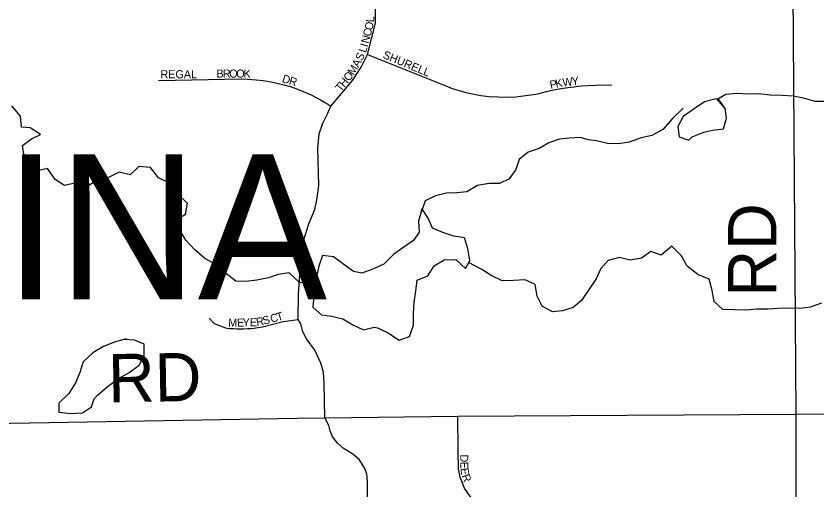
# Model space of a CAD drawing. Extents: x 1985906 to 2277390, y 930619 to 1324581.
# Drawn here: x 2148429 to 2153402, y 1155327 to 1158270 of the extents above; entities that cross this region are included whole.
import ezdxf

# ---------------------------------------------------------------- set-up
doc = ezdxf.new("R2010")
doc.units = 0
for name, color, linetype in [('GM_X_County_Road', 7, 'Continuous'), ('GM_X_County_Road_Text', 7, 'Continuous'), ('GM_X_Minor_Lake', 7, 'Continuous'), ('GM_X_Minor_River', 7, 'Continuous'), ('GM_X_Township_Road', 7, 'Continuous'), ('GM_X_Township_Road_Text', 7, 'Continuous'), ('GM_X_Township_Subdivision', 7, 'Continuous'), ('GM_X_Township_Subdivision_Text', 7, 'Continuous'), ('GM_X_Township_Text', 7, 'Continuous')]:
    doc.layers.add(name, color=color, linetype=linetype)

msp = doc.modelspace()

# ---------------------------------------------------------------- linework, layer by layer
at = {"layer": 'GM_X_County_Road'}
msp.add_lwpolyline([(2145952.7, 1155701.2), (2146258.9, 1155705.5), (2150174.8, 1155772.6), (2150347, 1155774.5), (2151172.5, 1155785.7), (2153272.3, 1155797.3), (2157154.1, 1155842.4)], dxfattribs=at)
at = {"layer": 'GM_X_Minor_Lake'}
for points in [[(2152782.6, 1157753.4), (2152776.9, 1157756.3), (2152705, 1157738.2), (2152639.1, 1157694.1), (2152571.3, 1157646), (2152539.3, 1157583.9), (2152547.3, 1157519.8), (2152607.3, 1157499.8)], [(2152607.3, 1157499.8), (2152627.2, 1157519.8), (2152699.1, 1157549.9), (2152753.1, 1157562), (2152821, 1157570), (2152840.9, 1157636.1), (2152832.9, 1157696.2), (2152790.9, 1157754.3)], [(2152607.3, 1157499.8), (2152627.2, 1157519.8), (2152699.1, 1157549.9), (2152753.1, 1157562), (2152821, 1157570), (2152840.9, 1157636.1), (2152832.9, 1157696.2), (2152782.6, 1157753.4)], [(2150949.6, 1157074.3), (2150949.6, 1157068.2), (2150927.7, 1156996.1), (2150931.7, 1156928), (2150897.8, 1156875.9), (2150835.9, 1156835.8), (2150774, 1156791.7), (2150712.1, 1156729.6), (2150644.2, 1156697.5), (2150576.3, 1156673.4), (2150524.3, 1156683.4), (2150464.4, 1156727.4), (2150400.5, 1156775.5), (2150332.6, 1156783.5), (2150308.6, 1156717.3), (2150294.7, 1156649.2), (2150282.7, 1156583.1), (2150278.7, 1156531), (2150270.8, 1156462.9), (2150324.7, 1156414.8), (2150388.6, 1156406.9), (2150458.5, 1156388.9), (2150520.5, 1156352.8), (2150586.4, 1156320.8), (2150652.3, 1156338.9)], [(2150945, 1157050.5), (2150949.6, 1157068.2), (2150927.7, 1156996.1), (2150931.7, 1156928), (2150897.8, 1156875.9), (2150835.9, 1156835.8), (2150774, 1156791.7), (2150712.1, 1156729.6), (2150644.2, 1156697.5), (2150576.3, 1156673.4), (2150524.3, 1156683.4), (2150464.4, 1156727.4), (2150400.5, 1156775.5), (2150332.6, 1156783.5), (2150308.6, 1156717.3), (2150294.7, 1156649.2), (2150282.7, 1156583.1), (2150278.7, 1156531), (2150270.8, 1156462.9), (2150324.7, 1156414.8), (2150388.6, 1156406.9), (2150458.5, 1156388.9), (2150520.5, 1156352.8), (2150586.4, 1156320.8), (2150652.3, 1156338.9)], [(2150652.3, 1156338.9), (2150672.3, 1156334.9), (2150736.2, 1156304.9), (2150808.1, 1156256.8), (2150872, 1156280.9), (2150896, 1156351), (2150896, 1156423.1), (2150901.9, 1156493.3), (2150911.9, 1156561.4), (2150919.8, 1156629.5), (2150985.7, 1156657.6), (2151025.7, 1156719.7), (2151087.6, 1156755.8), (2151159.5, 1156757.8), (2151219.4, 1156701.8), (2151247.4, 1156751.9), (2151233.4, 1156826), (2151213.3, 1156892.1), (2151147.4, 1156904.1), (2151079.5, 1156926.1), (2151015.6, 1156952.1), (2150987.6, 1157014.2), (2150949.6, 1157074.3)], [(2149112.4, 1156266), (2149040.5, 1156245.9), (2148972.6, 1156217.8), (2148904.7, 1156177.7), (2148844.8, 1156123.6), (2148824.8, 1156055.5), (2148798.9, 1155991.4), (2148757, 1155925.2), (2148695.1, 1155867.1), (2148695.1, 1155811), (2148769, 1155801), (2148840.9, 1155805.1), (2148896.8, 1155843.2), (2148914.8, 1155893.3)], [(2149096.4, 1156262), (2149040.5, 1156245.9), (2148972.6, 1156217.8), (2148904.7, 1156177.7), (2148844.8, 1156123.6), (2148824.8, 1156055.5), (2148798.9, 1155991.4), (2148757, 1155925.2), (2148695.1, 1155867.1), (2148695.1, 1155811), (2148769, 1155801), (2148840.9, 1155805.1), (2148896.8, 1155843.2), (2148914.8, 1155893.3)], [(2148914.8, 1155893.3), (2148936.7, 1155917.3), (2149002.6, 1155973.4), (2149064.5, 1156019.6), (2149128.4, 1156053.6), (2149194.3, 1156101.8), (2149224.3, 1156161.9), (2149224.2, 1156232), (2149164.3, 1156258), (2149096.4, 1156262)]]:
    msp.add_lwpolyline(points, dxfattribs=at)
at = {"layer": 'GM_X_Minor_River'}
for points in [[(2153457.2, 1157739.7), (2153391.3, 1157740.2), (2153318.9, 1157760.6), (2153254.7, 1157773.1), (2153186.7, 1157777.6), (2153112.8, 1157779.8), (2153042.7, 1157786.2), (2152976.9, 1157784.7), (2152904.9, 1157789.1), (2152837.1, 1157783.5), (2152787.5, 1157753.4)], [(2150283.3, 1156600), (2150188.1, 1156616.3), (2150124.9, 1156674.9), (2150057.2, 1156665.4), (2149995.8, 1156643.9), (2149924.2, 1156630.2), (2149856.5, 1156622.7), (2149792.6, 1156623.2), (2149729.5, 1156673.8), (2149674.4, 1156724.6), (2149601.6, 1156765), (2149536.5, 1156819.6), (2149483.2, 1156878.5), (2149445.8, 1156939.8), (2149422.4, 1157005.3), (2149481.5, 1157040.8), (2149493.9, 1157107.1), (2149426.6, 1157169.7), (2149381.2, 1157232.8), (2149312.5, 1157265.2), (2149263.1, 1157330.2), (2149191.1, 1157336.6), (2149138.4, 1157283.2), (2149068.1, 1157299.7), (2149003, 1157268.1), (2148933.5, 1157250.5), (2148870.5, 1157210.9), (2148802, 1157235.4), (2148730.5, 1157217.7), (2148671.8, 1157254.4), (2148624.3, 1157323.5), (2148560.7, 1157308), (2148506.2, 1157334.8), (2148478.7, 1157400.2), (2148469.2, 1157466.1), (2148524.2, 1157507.5), (2148581.5, 1157534.8), (2148516.6, 1157575.4), (2148462.6, 1157580.2), (2148457, 1157648.2), (2148401.6, 1157713)], [(2152571.5, 1157697.2), (2152505.1, 1157633.6), (2152444.7, 1157566.1), (2152377.7, 1157528.4), (2152310.2, 1157512.9), (2152236.9, 1157487.1), (2152169.2, 1157477.5), (2152101.3, 1157478), (2152033, 1157494.4), (2151983, 1157501.3), (2151932.7, 1157516.1), (2151864.9, 1157512.6), (2151803.2, 1157505.1), (2151737.7, 1157483.6), (2151676.7, 1157448.1), (2151609.3, 1157424.5), (2151552.4, 1157379.1), (2151531.9, 1157316.5), (2151491.3, 1157259.5), (2151430.1, 1157230), (2151366.2, 1157230.6), (2151294.5, 1157218.9), (2151227.5, 1157179.3), (2151165.8, 1157171.8), (2151102, 1157170.4), (2151032.5, 1157152.7), (2150969.2, 1157123.2), (2150945, 1157050.5)], [(2153430.1, 1156486.9), (2153360.8, 1156461.3), (2153297.1, 1156453.8), (2153225.1, 1156456.1), (2153159.3, 1156454.6), (2153099.5, 1156449.2), (2153029.6, 1156449.6), (2152959.8, 1156444), (2152891.9, 1156446.4), (2152817.9, 1156448.7), (2152764.9, 1156497.6), (2152751.3, 1156565.4), (2152733.7, 1156637.1), (2152663.2, 1156665.5), (2152596.1, 1156716.1), (2152558.6, 1156783.3), (2152501.3, 1156842.1), (2152434.8, 1156784.4), (2152370.3, 1156809), (2152313.4, 1156767.6), (2152241.8, 1156753.9), (2152175.5, 1156770.4), (2152106, 1156752.8), (2152059.3, 1156701.6), (2152030.8, 1156638.9), (2151988.3, 1156573.8), (2151940, 1156504.5), (2151889.1, 1156459.3), (2151821.7, 1156439.7), (2151759.9, 1156434.2), (2151695.2, 1156468.8), (2151665.8, 1156530.2), (2151652.2, 1156602.1), (2151589.6, 1156632.7), (2151517.8, 1156627), (2151448, 1156625.4), (2151383.4, 1156656), (2151320.5, 1156696.6), (2151238.1, 1156740.6)]]:
    msp.add_lwpolyline(points, dxfattribs=at)
at = {"layer": 'GM_X_Township_Road'}
for points in [[(2153272.3, 1155797.3), (2153236.1, 1161050.3)], [(2153292, 1152187.3), (2153286.3, 1152879.2), (2153280, 1153651.8), (2153273.4, 1154658.4), (2153272.3, 1155797.3)]]:
    msp.add_lwpolyline(points, dxfattribs=at)
at = {"layer": 'GM_X_Township_Subdivision'}
for points in [[(2150610.4, 1158032.4), (2150661.1, 1158226.7), (2150661.1, 1158350.6)], [(2150347, 1155774.5), (2150342.8, 1155990.3), (2150338.6, 1156059.3), (2150321.7, 1156114.2), (2150283.6, 1156194.5), (2150231.5, 1156264.9), (2150210.4, 1156308.5), (2150196.3, 1156357.9), (2150181.4, 1156386.7), (2150182.2, 1156545.2), (2150202, 1156804.3), (2150216, 1156880.3), (2150247, 1156978.9), (2150283.6, 1157069), (2150297.7, 1157139.5), (2150309, 1157218.3), (2150303.3, 1157449.3), (2150311.8, 1157539.5), (2150334.3, 1157604.2), (2150362.5, 1157663.4), (2150384, 1157710.8), (2150517.4, 1157869), (2150570.9, 1157953.5), (2150610.4, 1158032.4)], [(2150610.4, 1158032.4), (2151066.4, 1157848.6), (2151097.2, 1157836), (2151137.3, 1157821.2), (2151179.7, 1157807.7), (2151222, 1157796.2), (2151273.5, 1157785), (2151315, 1157777.8), (2151365.7, 1157771.6), (2151422.4, 1157767.7), (2151481.2, 1157767.1), (2151532.3, 1157769.4), (2151595.3, 1157775.8), (2151656, 1157785.8), (2151692.3, 1157793.7), (2151723.1, 1157801.3), (2151748.5, 1157807), (2151779.3, 1157813.4), (2151800.8, 1157817.4), (2151839.8, 1157823.9), (2151871.3, 1157828.4), (2151895.2, 1157831.3), (2151918.9, 1157833.9), (2151940.9, 1157835.9), (2151977.5, 1157838.5), (2152027.2, 1157840.7), (2152128.2, 1157842.4)], [(2149312.5, 1157870.5), (2149826.7, 1157879.3), (2149865.8, 1157878.6), (2149920.2, 1157875), (2149963, 1157870.1), (2150022.8, 1157860), (2150084.2, 1157845.8), (2150138.6, 1157829.7), (2150187.4, 1157812.3), (2150261, 1157780.5), (2150319.8, 1157749.7), (2150358.5, 1157726.7), (2150384, 1157710.8)], [(2149627.4, 1156394.5), (2149659.7, 1156360.6), (2149729.3, 1156333.3), (2149740.4, 1156332.1), (2149755, 1156330.7), (2149768.9, 1156329.7), (2149781.4, 1156329), (2149798.1, 1156328.3), (2149820.3, 1156328), (2149843.2, 1156328.3), (2149866.5, 1156329.3), (2149885.9, 1156330.6), (2149905.7, 1156332.5), (2149931.2, 1156335.6), (2149958.6, 1156339.9), (2150087.9, 1156373.3), (2150181.4, 1156386.7)], [(2150299.5, 1154598.2), (2150505.9, 1154805.6), (2150537.2, 1154846.3), (2150564.7, 1154921.8), (2150594.9, 1155031.9), (2150611.8, 1155120.4), (2150612, 1155211.8), (2150612.2, 1155380.5), (2150607.2, 1155424.9), (2150595.6, 1155460.5), (2150561.1, 1155514.2), (2150520.4, 1155548.9), (2150461, 1155587.2), (2150423.1, 1155618.8), (2150393.7, 1155659.5), (2150378.5, 1155694.9), (2150371.1, 1155727.9), (2150347, 1155774.5)], [(2151266.1, 1155263.8), (2151214.1, 1155338.7), (2151187.1, 1155407.3), (2151176.7, 1155457.2), (2151174.6, 1155569.5), (2151172.5, 1155785.7)]]:
    msp.add_lwpolyline(points, dxfattribs=at)

# ---------------------------------------------------------------- texts
at = {"layer": 'GM_X_County_Road_Text'}
msp.add_text('RD', height=300, rotation=0.9872, dxfattribs=at).set_placement((2149002.5, 1155870.5))
at = {"layer": 'GM_X_Township_Road_Text'}
msp.add_text('RD', height=300, rotation=90, dxfattribs=at).set_placement((2153150, 1156528.1))
at = {"layer": 'GM_X_Township_Subdivision_Text'}
for s, rotation, p in [('L', 87.1508, (2150652, 1158231.1)), ('C', 74.8918, (2150629.4, 1158138.7)), ('O', 76.2488, (2150640, 1158178.2)), ('N', 74.902, (2150617.9, 1158096.2)), ('I', 74.7691, (2150612.1, 1158074.8)), ('S', 64.5481, (2150577.5, 1157988.3)), ('L', 72.4294, (2150600.9, 1158039.1)), ('SHURELL', 337.5197, (2150702.1, 1158010.8)), ('A', 61.597, (2150555.3, 1157947.1)), ('M', 57.8454, (2150525.4, 1157899.4)), ('REGAL', 0, (2149325.7, 1157883.9)), ('B', 359.8786, (2149673.2, 1157888.3)), ('R', 359.8991, (2149712.9, 1157888.2)), ('O', 359.8907, (2149752.5, 1157888.1)), ('O', 359.8907, (2149796.4, 1157888)), ('K', 358.3166, (2149840.1, 1157888)), ('D', 341.7516, (2150076.7, 1157861.4)), ('R', 343.1622, (2150119.7, 1157847.2)), ('O', 54.1891, (2150497.7, 1157860.8)), ('Y', 5.4279, (2151881.4, 1157839.6)), ('T', 50.3204, (2150444.8, 1157796.9)), ('H', 50.3092, (2150467.3, 1157824)), ('P', 11.2188, (2151748.2, 1157817.7)), ('K', 10.9499, (2151782.7, 1157824.5)), ('W', 6.977, (2151825, 1157832.7)), ('R', 10.4691, (2149924.2, 1156344.9)), ('S', 14.4558, (2149966.8, 1156353)), ('C', 14.5723, (2150013.8, 1156365.1)), ('T', 16.3265, (2150053.7, 1156375.5)), ('M', 359.1438, (2149746.3, 1156341.6)), ('E', 1.4759, (2149801.3, 1156340.9)), ('Y', 1.4425, (2149836.5, 1156341.8)), ('E', 1.9022, (2149880.9, 1156342.9)), ('D', 270.4591, (2151186.8, 1155546.8)), ('E', 270.4514, (2151187.2, 1155502.8)), ('E', 278.2432, (2151188, 1155460.3)), ('R', 288.8927, (2151195.4, 1155415.8))]:
    msp.add_text(s, height=50, rotation=rotation, dxfattribs=at).set_placement(p)
at = {"layer": 'GM_X_Township_Text'}
msp.add_text('MEDINA', height=900, rotation=0, dxfattribs=at).set_placement((2145679.4, 1156510.7))

doc.saveas('drawing.dxf')
